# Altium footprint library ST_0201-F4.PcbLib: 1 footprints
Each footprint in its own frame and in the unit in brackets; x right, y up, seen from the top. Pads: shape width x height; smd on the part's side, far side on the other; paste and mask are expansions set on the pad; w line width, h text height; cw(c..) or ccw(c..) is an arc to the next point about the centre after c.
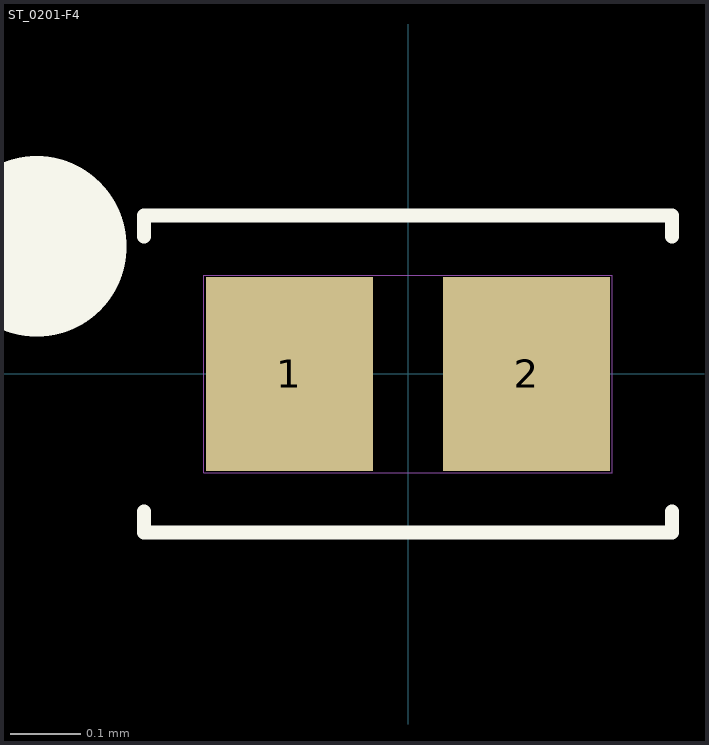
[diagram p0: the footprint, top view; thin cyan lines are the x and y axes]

## ST_0201-F4 [mm] "ST_0201-F4"
pads (2):
  rect 0.237x0.275 smd paste-20 mask-0.025: 1(-0.169,0) 2(0.168,0)
Top Overlay:
  circle w0.254: c-0.528,0.181 r0.001
  lines w0.02: -0.375,-0.195 -0.375,-0.225 0.375,-0.225 0.375,-0.195 ; -0.375,0.195 -0.375,0.225 0.375,0.225 0.375,0.195
Top Paste:
  rectangle: -0.253,-0.105 -0.083,0.105
  rectangle: 0.083,-0.105 0.253,0.105
Mechanical 5:
  text "1" at -0.191,-0.37 h0.05
  text "2" at 0.211,-0.355 h0.05
Mechanical 6:
  lines w0: -0.29,-0.14 -0.29,0.14 0.29,0.14 0.29,-0.14 -0.29,-0.14
Mechanical 7:
  lines w0: -0.29,-0.14 0.29,-0.14 0.29,0.14 -0.29,0.14 -0.29,-0.14
3D body: height 0.32, standoff 0, extent -0.29,-0.14 0.29,0.14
